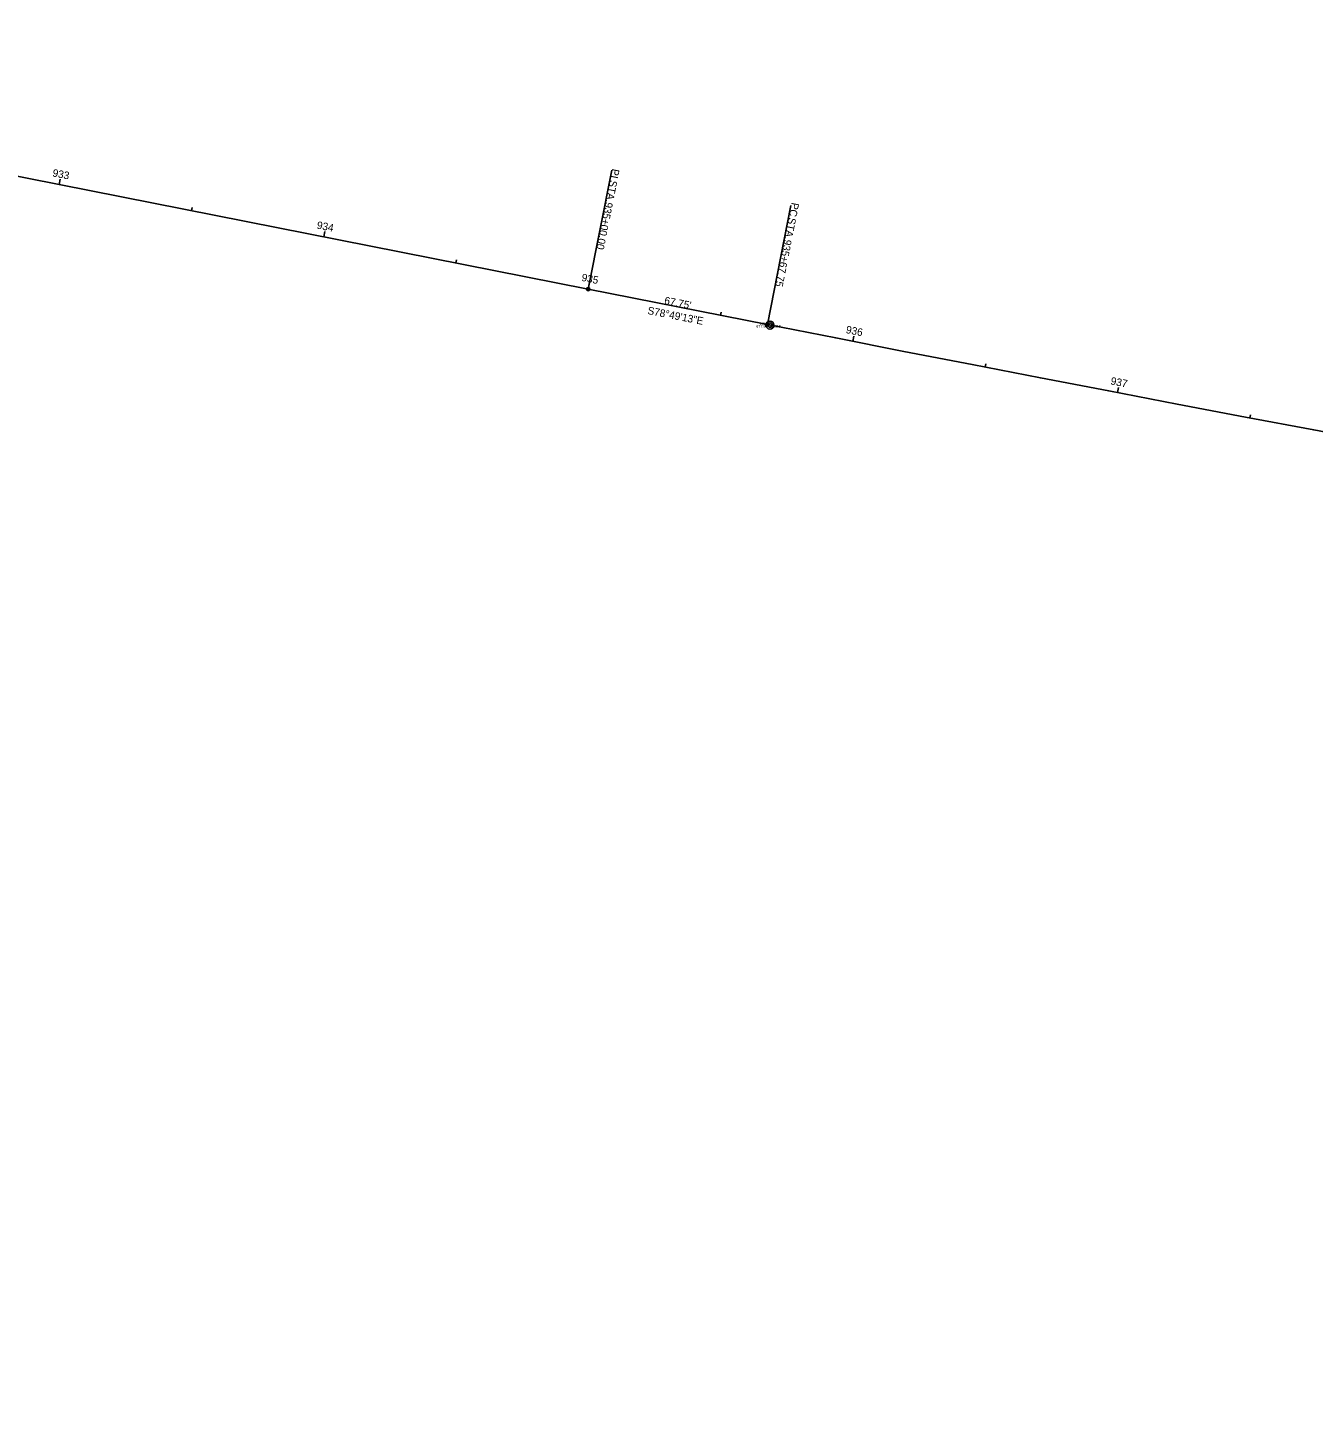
# Model space of a CAD drawing. Extents: x 2061744 to 2069155, y 709240 to 710416.
# Drawn here: x 2064972 to 2065448, y 709273 to 709788 of the extents above; entities that cross this region are included whole.
import ezdxf

# ---------------------------------------------------------------- set-up
doc = ezdxf.new("R2010")
doc.units = 0
for name, color, linetype in [('RS_Raster1', 7, 'Continuous'), ('RW_X_CL', 7, 'Continuous'), ('RW_X_CL_100_Bearings', 7, 'Continuous'), ('RW_X_CL_100_Cardinal_Points', 7, 'Continuous'), ('RW_X_CL_100_Distances', 7, 'Continuous'), ('RW_X_CL_100_Stations', 7, 'Continuous'), ('SV_X_Mon_Cells_Found', 7, 'Continuous'), ('SV_X_Text_Comment', 7, 'Continuous'), ('SV_X_Text_Elevation', 7, 'Continuous'), ('SV_X_Text_Name', 7, 'Continuous')]:
    doc.layers.add(name, color=color, linetype=linetype)

msp = doc.modelspace()

# ---------------------------------------------------------------- linework, layer by layer
at = {"layer": 'RS_Raster1'}
for p, q in [((2064688.97, 709788.32), (2065179.48, 709691.38)), ((2065179.48, 709691.38), (2065245.94, 709678.24))]:
    msp.add_line(p, q, dxfattribs=at)
msp.add_arc((2069689.49, 732161.85), 22918.5, 258.820408, 267.070408, dxfattribs=at)
at = {"layer": 'RW_X_CL'}
for p, q in [((2064688.97, 709788.32), (2065179.48, 709691.38)), ((2065179.48, 709691.38), (2065245.94, 709678.24))]:
    msp.add_line(p, q, dxfattribs=at)
msp.add_arc((2069689.49, 732161.85), 22918.5, 258.820408, 267.070408, dxfattribs=at)
at = {"layer": 'RW_X_CL_100_Cardinal_Points'}
for p, q in [((2065179.48, 709691.38), (2065188.2, 709735.53)), ((2065245.94, 709678.24), (2065254.67, 709722.39))]:
    msp.add_line(p, q, dxfattribs=at)
for centre in [(2065179.48, 709691.38), (2065245.94, 709678.24)]:
    msp.add_circle(centre, 0.6, dxfattribs=at)
at = {"layer": 'RW_X_CL_100_Stations'}
for p, q in [((2064983.27, 709730.16), (2064983.66, 709732.12)), ((2065032.32, 709720.46), (2065032.56, 709721.64)), ((2065081.38, 709710.77), (2065081.76, 709712.73)), ((2065130.43, 709701.07), (2065130.66, 709702.25)), ((2065179.48, 709691.38), (2065179.87, 709693.34)), ((2065228.53, 709681.69), (2065228.76, 709682.86)), ((2065277.59, 709672.01), (2065277.97, 709673.98)), ((2065326.66, 709662.44), (2065326.89, 709663.62)), ((2065375.76, 709652.98), (2065376.13, 709654.94)), ((2065424.87, 709643.62), (2065425.1, 709644.8))]:
    msp.add_line(p, q, dxfattribs=at)
at = {"layer": 'SV_X_Mon_Cells_Found'}
for radius in [1.5, 0.8]:
    msp.add_circle((2065246.85, 709678.02), radius, dxfattribs=at)

# ---------------------------------------------------------------- texts
at = {"layer": 'RW_X_CL_100_Bearings'}
msp.add_text('S78°49\'13"E', height=2.8, rotation=348.8204, dxfattribs=at).set_placement((2065201.27, 709682.18))
at = {"layer": 'RW_X_CL_100_Cardinal_Points'}
for s, p in [('PI', (2065188.37, 709736.2)), (' STA. ', (2065187.73, 709732.95)), ('935+00.00', (2065185.92, 709723.8)), ('PC', (2065254.95, 709723.64)), (' STA. ', (2065254.06, 709719.12)), ('935+67.75', (2065252.25, 709709.98))]:
    msp.add_text(s, height=2.8, rotation=258.8204, dxfattribs=at).set_placement(p)
at = {"layer": 'RW_X_CL_100_Distances'}
msp.add_text("67.75'", height=2.8, rotation=348.8204, dxfattribs=at).set_placement((2065207.5, 709685.88))
at = {"layer": 'RW_X_CL_100_Stations'}
for s, rotation, p in [('933', 348.8204, (2064980.62, 709733.23)), ('934', 348.8204, (2065078.64, 709713.86)), ('935', 348.8204, (2065176.82, 709694.45)), ('936', 348.901, (2065274.87, 709675.09)), ('937', 349.151, (2065373.04, 709656.04))]:
    msp.add_text(s, height=2.8, rotation=rotation, dxfattribs=at).set_placement(p)
at = {"layer": 'SV_X_Text_Comment'}
msp.add_text('CMON', height=1, dxfattribs=at).set_placement((2065246.85, 709677.02))
at = {"layer": 'SV_X_Text_Elevation'}
msp.add_text('977.942', height=1, dxfattribs=at).set_placement((2065241.77, 709677.02))
at = {"layer": 'SV_X_Text_Name'}
msp.add_text('MN02', height=1, dxfattribs=at).set_placement((2065243.02, 709678.02))

doc.saveas('drawing.dxf')
